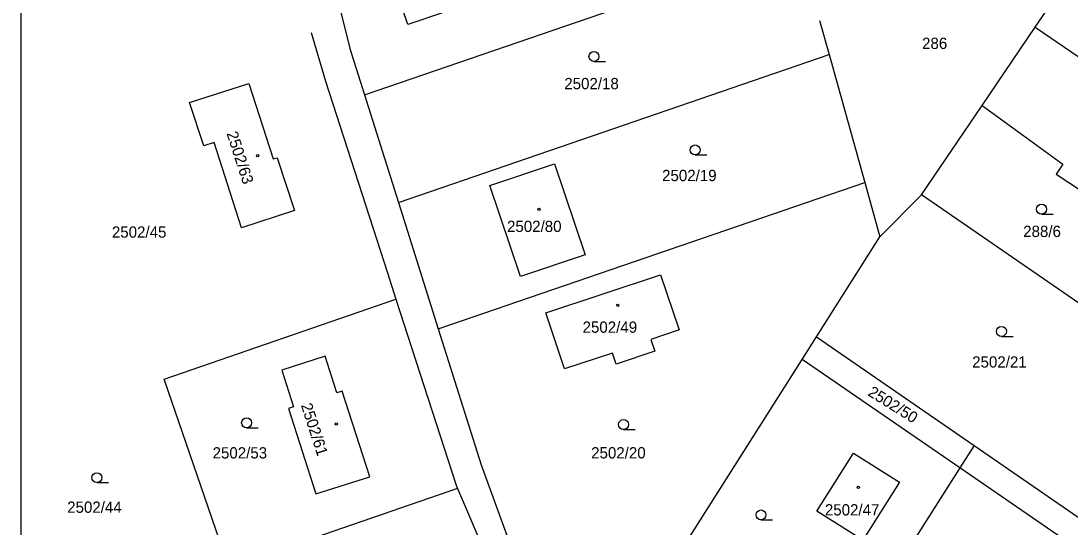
# Model space of a CAD drawing. Extents: x -558358 to -557517, y -1073786 to -1073189.
# Drawn here: x -558357.5 to -558199.4, y -1073422.1 to -1073345.8 of the extents above; entities that cross this region are included whole.
import ezdxf

# ---------------------------------------------------------------- set-up
doc = ezdxf.new("R2010")
doc.units = 0
for name, color, linetype in [('Hranice parcel', 7, 'Continuous'), ('Parcelní čísla', 7, 'Continuous'), ('Vrstva 1', 7, 'Continuous'), ('Značky budov', 7, 'Continuous'), ('Značky kultur', 7, 'Continuous')]:
    doc.layers.add(name, color=color, linetype=linetype)

msp = doc.modelspace()

# ---------------------------------------------------------------- linework, layer by layer
at = {"layer": 'Hranice parcel'}
for p, q in [((-558305.76, -1073356.92), (-558240.15, -1073334.41)), ((-558204.65, -1073346.74), (-558196.91, -1073335.32)), ((-558237.16, -1073345.74), (-558235.73, -1073350.87)), ((-558212.67, -1073358.56), (-558204.65, -1073346.74)), ((-558204.65, -1073346.74), (-558176.94, -1073365.71)), ((-558300.65, -1073373.14), (-558235.73, -1073350.87)), ((-558235.73, -1073350.87), (-558230.35, -1073370.17)), ((-558305.76, -1073356.92), (-558300.65, -1073373.14)), ((-558221.79, -1073372.01), (-558212.67, -1073358.56)), ((-558212.67, -1073358.56), (-558200.47, -1073367.38)), ((-558294.64, -1073392.22), (-558230.35, -1073370.17)), ((-558230.35, -1073370.17), (-558228.07, -1073378.34)), ((-558228.07, -1073378.34), (-558221.79, -1073372.01)), ((-558193.18, -1073391.75), (-558221.79, -1073372.01)), ((-558300.65, -1073373.14), (-558294.64, -1073392.22)), ((-558237.63, -1073393.44), (-558228.07, -1073378.34)), ((-558302.31, -1073383.75), (-558301.02, -1073387.75)), ((-558335.97, -1073399.79), (-558301.02, -1073387.75)), ((-558294.64, -1073392.22), (-558288.18, -1073412.71)), ((-558239.77, -1073396.82), (-558237.63, -1073393.44)), ((-558237.63, -1073393.44), (-558213.88, -1073409.79)), ((-558257.7, -1073425.14), (-558239.77, -1073396.82)), ((-558216.02, -1073413.17), (-558239.77, -1073396.82)), ((-558326.19, -1073428.15), (-558335.97, -1073399.79)), ((-558213.88, -1073409.79), (-558216.02, -1073413.17)), ((-558213.88, -1073409.79), (-558196.71, -1073421.6)), ((-558288.18, -1073412.71), (-558274.97, -1073448.74)), ((-558216.02, -1073413.17), (-558233.8, -1073441.26)), ((-558291.74, -1073416.28), (-558326.19, -1073428.15)), ((-558291.74, -1073416.28), (-558280.07, -1073443.5))]:
    msp.add_line(p, q, dxfattribs=at)
for points in [[(-558302.49, -1073336.69), (-558282.13, -1073329.71), (-558282.06, -1073329.92), (-558279.49, -1073329.04), (-558277.55, -1073334.7), (-558280.12, -1073335.56), (-558280.04, -1073335.79), (-558289.36, -1073338.99), (-558288.15, -1073342.54), (-558299.21, -1073346.34), (-558302.49, -1073336.69)], [(-558311.02, -1073337.58), (-558307.96, -1073349.92), (-558305.76, -1073356.92)], [(-558313.78, -1073347.52), (-558311.65, -1073354.86), (-558302.31, -1073383.75)], [(-558329.99, -1073364.63), (-558332.12, -1073358.09), (-558323.21, -1073355.2), (-558319.51, -1073366.6), (-558318.91, -1073366.43), (-558316.33, -1073374.39), (-558324.28, -1073376.97), (-558328.43, -1073364.14), (-558329.99, -1073364.63)], [(-558282.25, -1073384.34), (-558286.86, -1073370.59), (-558277.14, -1073367.32), (-558272.5, -1073381.07), (-558282.25, -1073384.34)], [(-558200.47, -1073367.38), (-558201.52, -1073368.91), (-558186.39, -1073378.87)], [(-558278.42, -1073389.81), (-558261.13, -1073384.05), (-558258.31, -1073392.37), (-558262.58, -1073393.82), (-558262, -1073395.6), (-558267.81, -1073397.55), (-558268.37, -1073395.87), (-558275.59, -1073398.26), (-558278.42, -1073389.81)], [(-558301.02, -1073387.75), (-558291.95, -1073415.8), (-558291.74, -1073416.28)], [(-558309.9, -1073401.85), (-558311.67, -1073396.36), (-558318.22, -1073398.44), (-558316.44, -1073403.96), (-558317.23, -1073404.23), (-558313.09, -1073417.12), (-558304.96, -1073414.53), (-558309.1, -1073401.61), (-558309.9, -1073401.85)], [(-558232.07, -1073410.99), (-558225.13, -1073415.34), (-558230.62, -1073424.08), (-558237.55, -1073419.73), (-558232.07, -1073410.99)], [(-558202.26, -1073462.53), (-558188.73, -1073442.87), (-558187.31, -1073436.01), (-558191.04, -1073430.36), (-558216.02, -1073413.17)]]:
    msp.add_lwpolyline(points, dxfattribs=at)
at = {"layer": 'Vrstva 1'}
msp.add_line((-558357.53, -1073784.09), (-558357.53, -1073190.09), dxfattribs=at)
at = {"layer": 'Značky budov'}
for centre in [(-558321.85, -1073366.12), (-558279.47, -1073374.21), (-558267.57, -1073388.69), (-558310.02, -1073406.56), (-558231.33, -1073416.12)]:
    msp.add_circle(centre, 0.175, dxfattribs=at)
at = {"layer": 'Značky kultur'}
for p, q in [((-558271.17, -1073351.89), (-558269.42, -1073351.89)), ((-558255.92, -1073365.99), (-558254.17, -1073365.99)), ((-558203.7, -1073374.92), (-558201.95, -1073374.92)), ((-558209.75, -1073393.36), (-558208, -1073393.36)), ((-558323.52, -1073407.14), (-558321.77, -1073407.14)), ((-558266.71, -1073407.4), (-558264.96, -1073407.4)), ((-558346.09, -1073415.41), (-558344.34, -1073415.41)), ((-558245.99, -1073421.03), (-558244.24, -1073421.03))]:
    msp.add_line(p, q, dxfattribs=at)
for centre in [(-558271.17, -1073351.14), (-558255.92, -1073365.24), (-558203.7, -1073374.17), (-558209.75, -1073392.61), (-558323.52, -1073406.39), (-558266.71, -1073406.65), (-558346.09, -1073414.66), (-558245.99, -1073420.28)]:
    msp.add_circle(centre, 0.75, dxfattribs=at)

# ---------------------------------------------------------------- texts
at = {"layer": 'Parcelní čísla'}
for s, p in [('286', (-558221.71, -1073350.01)), ('2502/18', (-558275.64, -1073356.08)), ('2502/19', (-558260.9, -1073369.94)), ('2502/45', (-558343.83, -1073378.47)), ('2502/80', (-558284.27, -1073377.61)), ('288/6', (-558206.47, -1073378.37)), ('2502/49', (-558272.88, -1073392.81)), ('2502/21', (-558214.16, -1073398.06)), ('2502/53', (-558328.65, -1073411.77)), ('2502/20', (-558271.59, -1073411.76)), ('2502/44', (-558350.57, -1073419.96)), ('2502/47', (-558236.36, -1073420.36))]:
    msp.add_text(s, height=1.7, dxfattribs=at).set_placement(p)
for s, rotation, p in [('2502/63', 288, (-558326.57, -1073362.74)), ('2502/50', 328, (-558230.02, -1073402.18)), ('2502/61', 288, (-558315.36, -1073403.73))]:
    msp.add_text(s, height=1.7, rotation=rotation, dxfattribs=at).set_placement(p)

doc.saveas('drawing.dxf')
